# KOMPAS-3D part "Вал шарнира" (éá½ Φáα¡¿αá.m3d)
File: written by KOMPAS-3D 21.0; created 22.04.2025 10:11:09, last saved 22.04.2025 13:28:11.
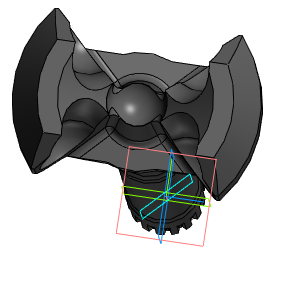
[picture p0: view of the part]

Document properties: Полное имя файла: D:\OLIMPGM-2025№1\Г-413\413-06\Вал шарнира.m3d; Автор: adm

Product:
- Part/product: Вал шарнира
    Материал: Сталь 27ХГР ГОСТ 4543-2016 (density 7850 kg/m3)
    Масса: 9.069085
    Форматы листов документа: A2
  - Body: Поверхность 10
      Материал: Сталь 27ХГР ГОСТ 4543-2016 (density 0 kg/m3)
  - Body: Поверхность 7
      Материал: Сталь 27ХГР ГОСТ 4543-2016 (density 0 kg/m3)

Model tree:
1. Эскиз:1
2. Элемент вращения:1
     Угол 1 = 360
3. Эскиз:2
4. Элемент выдавливания:1
     Расстояние 2 = 42
5. Эскиз:3
6. Элемент вращения:2
     Угол 1 = 360
7. Эскиз:4  (with: Элемент вращения:1)
8. Элемент выдавливания:2
     Расстояние 1 = 200
9. Эскиз:5  (with: Элемент вращения:1)
10. Элемент выдавливания:3
     Расстояние 2 = 84
11. Средняя плоскость:1
12. Эскиз:6
13. Элемент вращения:3
     Угол 1 = 360
14. Эскиз:7
15. Элемент по траектории:1
16. Массив по концентрической сетке:1  (with: Элемент по траектории:1)  (2 pattern instances)
     Шаг 2 = 90
17. Эскиз:8  (with: Элемент вращения:1, Элемент выдавливания:3)
18. Элемент вращения:4
     Угол 1 = 360
19. Эскиз:9  (with: Элемент выдавливания:2)
20. Эскиз:12  (with: Элемент выдавливания:2)
21. Элемент вращения:5
     Угол 1 = 360
22. Эскиз:13  (with: Элемент выдавливания:2, Элемент по траектории:1)
23. Элемент вращения:6
     Угол 1 = 360
24. Скругление:1  (with: Элемент вращения:4)
     Радиус = 4
25. Эскиз:17  (with: Элемент выдавливания:2, Элемент выдавливания:3)
26. Эскиз:18  (with: Элемент выдавливания:3, Элемент вращения:4)
27. Элемент выдавливания:5  (with: Элемент вращения:1)
     Расстояние 1 = -9.5
28. Эскиз:20  (with: Элемент выдавливания:2)
29. Поверхность выдавливания:4  (with: Элемент выдавливания:3)
     Расстояние 1 = 24.3238; Расстояние 2 = 24.3238
30. Придать толщину:5  (with: Поверхность выдавливания:4)
     Толщина стенки 1 = 5
31. Эскиз:23  (with: Элемент вращения:1, Элемент выдавливания:3, Элемент выдавливания:5)
32. Поверхность выдавливания:6
     Расстояние 1 = 40
33. Эскиз:21  (with: Элемент выдавливания:5)
34. Элемент вращения:7
     Угол 1 = 360
35. Эскиз:22
36. Придать толщину:6  (with: Поверхность выдавливания:6)
     Толщина стенки 1 = 25
37. Булева операция:5
38. Зеркальное отражение:1
39. Экземпляр ( 1 )
40. Экземпляр ( 2 )
41. Тело 11
42. Элемент выдавливания:6
     Расстояние 1 = 46.25; Расстояние 2 = 46.25
43. Булева операция:6
44. Скругление:3  (with: Булева операция:6)  (labels: Сталь 27ХГР ГОСТ 4543-2016)
     Радиус = 5

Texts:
  Точка начала. Х
  Точка начала. Y
  Точка начала. Z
